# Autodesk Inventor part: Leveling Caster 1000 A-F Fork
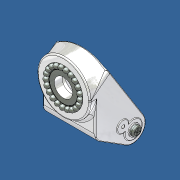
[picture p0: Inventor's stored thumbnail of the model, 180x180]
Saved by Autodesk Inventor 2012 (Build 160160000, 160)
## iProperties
Created: 2015-01
Part Number: Leveling Caster 1000 A-F Fork
Material: Default
Document SubType Name: Modeling
Designer: Admin
Density: 1 g/cm^3
Author: Admin
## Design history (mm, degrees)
feature "Base1"
body "Solid1"
